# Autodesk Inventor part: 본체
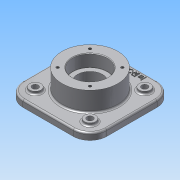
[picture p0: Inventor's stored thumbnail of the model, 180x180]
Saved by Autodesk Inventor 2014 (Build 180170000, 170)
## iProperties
Created: 2015-09
Part Number: 본체
Material: 알루미늄 6061
Document SubType Name: Modeling
Designer: study
Density: 2.71 g/cm^3
Appearance: 알루미늄 - 평지
Author: study
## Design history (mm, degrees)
sketch "스케치1"
  geometry: L1 (45, -75)-(-45, -75); L2 (-75, -45)-(-75, 45); L3 (-45, 75)-(45, 75); L4 (75, 45)-(75, -45); L5 (75, -75)-(-75, 75); L6 (-75, -75)-(75, 75); A1 r 30 centre (-45, 45) between (-45, 75) and (-75, 45); A2 r 30 centre (45, 45) between (75, 45) and (45, 75); A3 r 30 centre (45, -45) between (45, -75) and (75, -45); A4 r 30 centre (-45, -45) between (-75, -45) and (-45, -75); 3 further points
  constraints: 12 end point, 8 point on circle, 8 point on line, 8 tangent, 4 centre point, 3 equal radius, 3 midpoint, 2 parallel, 2 perpendicular, 1 coincident, 1 horizontal
  dimensions: "d0" = 150 distance of L5.end L6.end; "d3" = 30 radius of A1
extrude "돌출1" new body sketch "스케치1" distance "d1" = 12; taper "d2" = 0 deg
sketch "스케치2"
  geometry: L1 (49, -49)-(-49, -49); L2 (-49, -49)-(-49, 49); L3 (-49, 49)-(49, 49); L4 (49, 49)-(49, -49); L5 (49, -49)-(-49, 49); L6 (-49, -49)-(49, 49); C1 r 10 at (-49, 49); C2 r 10 at (49, 49); C3 r 10 at (-49, -49); C4 r 10 at (49, -49); 3 further points
  constraints: 12 end point, 5 coincident, 4 centre point, 3 equal radius, 3 midpoint, 2 parallel, 1 horizontal, 1 perpendicular
  dimensions: "d4" = 98 distance of L2.end L3.end; "d5" = 98 distance of L3.end L1.start; "d6" = 20 diameter of C1
extrude "돌출2" join sketch "스케치2" distance "d7" = 5; taper "d8" = 0 deg
sketch "스케치3"
  geometry: C1 r 10 at (0, 0) reference; C2 r 10 at (0, -98) reference; C3 r 10 at (98, -98) reference; C4 r 10 at (98, 0) reference; 1 further point
hole "구멍1" sketch "스케치3" at (0, -98), (0, 0), (98, 0), (98, -98) diameter "d9" = 11; stored, may be unused: countersink angle "d13" = 90 deg, drill point angle "d15" = 118 deg; dims "d10" = 6, "d11" = 4, "d12" = 2, "d14" = 8
node "작업 평면1"
sketch "스케치5"
  geometry: C1 r 50 at (0, 0); 1 further point
  constraints: 1 centre point, 1 coincident
  dimensions: "d17" = 100 diameter of C1
extrude "돌출3" join sketch "스케치5" distance "d18" = 70; taper "d19" = 0 deg
hole "구멍2" diameter "d22" = 45; stored, may be unused: countersink angle "d26" = 90 deg, drill point angle "d28" = 118 deg; dims "d20" = 10, "d21" = 10, "d23" = 6, "d24" = 62, "d25" = 22, "d27" = 8
sketch "스케치6"
  geometry: L1 (28.991, -28.991)-(-28.991, -28.991); L2 (-28.991, -28.991)-(-28.991, 28.991); L3 (-28.991, 28.991)-(28.991, 28.991); L4 (28.991, 28.991)-(28.991, -28.991); L5 (28.991, -28.991)-(-28.991, 28.991); L6 (-28.991, -28.991)-(28.991, 28.991); C1 r 50 at (0, 0) reference; 4 further points
  constraints: 12 end point, 4 coincident, 2 midpoint, 2 parallel, 2 perpendicular, 1 horizontal
  dimensions: "d30" = 82 distance of L1.end L3.end
hole "구멍3" sketch "스케치6" at (-28.991, 28.991), (-28.991, -28.991), (28.991, -28.991), (28.991, 28.991) diameter "d31" = 4.917; stored, may be unused: countersink angle "d35" = 90 deg, drill point angle "d37" = 118 deg; dims "d32" = 10, "d33" = 62, "d34" = 22, "d36" = 13
node "작업 평면2"
sketch "스케치7"
  geometry: C1 r 50 at (0, 0) reference; 1 further point
  constraints: 1 vertical alignment, 1 other
  dimensions: "d38" = 65 distance of point (0, 65) C1.centre
feature "엠보싱1" sketch "스케치7" dims "d0" = 150, "d3" = 30, "d39" = 1, "d40" = 0
fillet "모깎기1" dims "d41" = 0.3, "d42" = 3
chamfer "모따기1" distance "d43" = 1; stored, may be unused: second distance "d44" = 2, angle "d45" = 45 deg
node "솔리드1"
mirror "대칭1"
node "투영된 루프1"
node "투영된 루프2"
node "투영된 루프3"
other parameters: "d16" = 23
